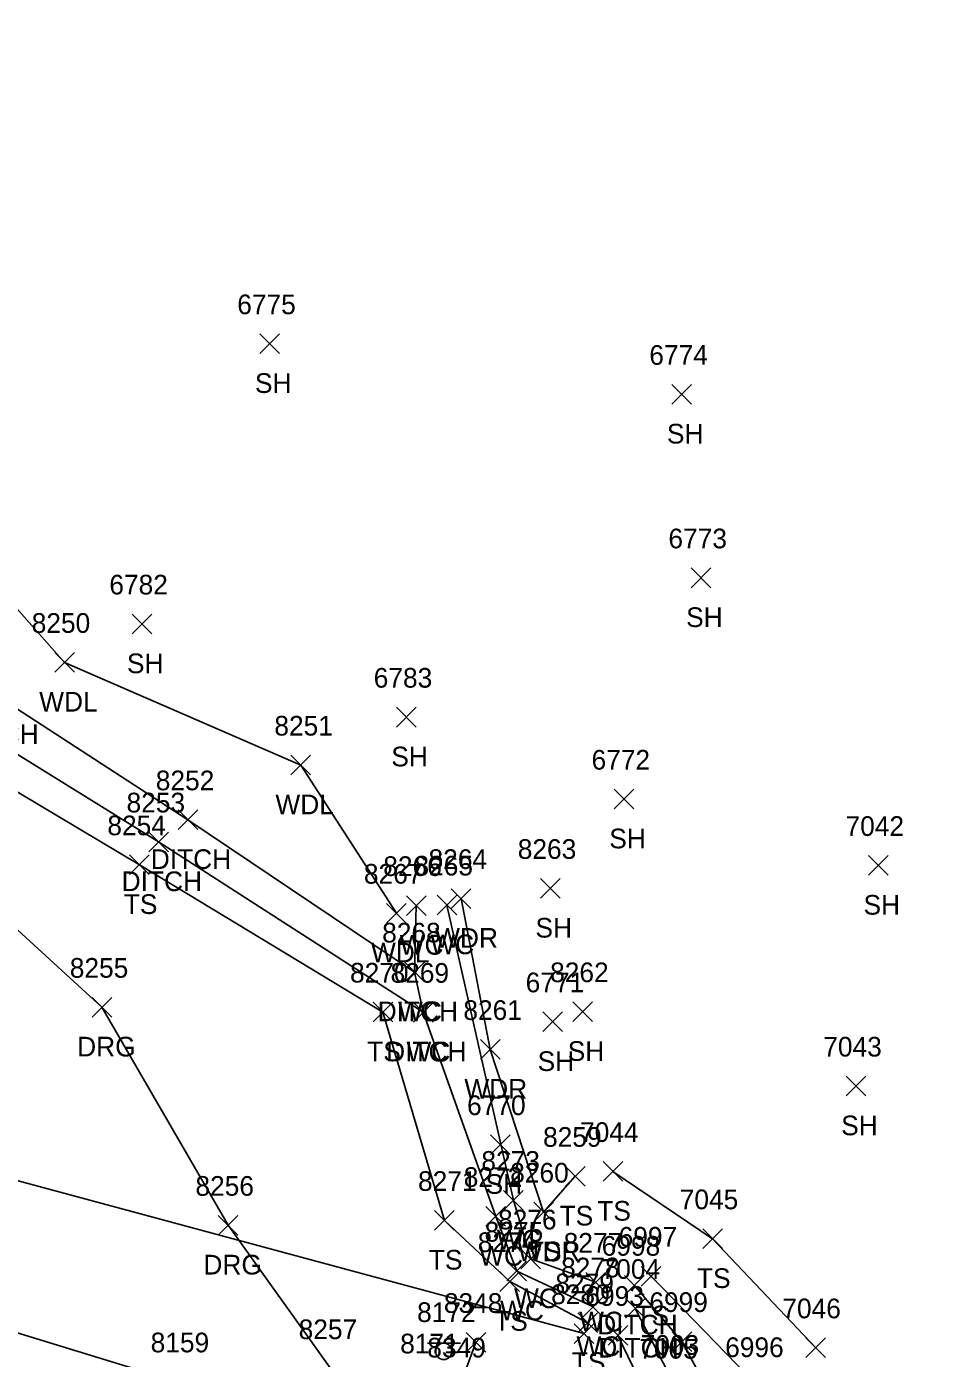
# Model space of a CAD drawing. Extents: x 1588028 to 1589597, y 137576 to 138176.
# Drawn here: x 1589112.3 to 1589205.2, y 137833.8 to 137969.2 of the extents above; entities that cross this region are included whole.
import ezdxf

# ---------------------------------------------------------------- set-up
doc = ezdxf.new("R2010")
doc.units = 0
for name, color, linetype in [('D_A', 7, 'Continuous'), ('D_I', 7, 'Continuous'), ('D_TIC', 7, 'Continuous'), ('DCP', 7, 'Continuous'), ('DD', 7, 'Continuous'), ('L_A', 7, 'Continuous'), ('L_I', 7, 'Continuous'), ('L_TIC', 7, 'Continuous'), ('LAWA', 7, 'Continuous'), ('LAWE', 7, 'Continuous'), ('LELB', 7, 'Continuous'), ('P_I', 7, 'Continuous'), ('PET', 7, 'Continuous'), ('R_A', 7, 'Continuous'), ('R_I', 7, 'Continuous'), ('R_TIC', 7, 'Continuous'), ('RDG', 7, 'Continuous'), ('S_I', 7, 'Continuous'), ('SSGN', 7, 'Continuous')]:
    doc.layers.add(name, color=color, linetype=linetype)

msp = doc.modelspace()

# ---------------------------------------------------------------- linework, layer by layer
at = {"layer": 'D_TIC'}
for points in [[(1589127.72, 137887.57), (1589129.72, 137889.57)], [(1589129.72, 137887.57), (1589127.72, 137889.57)], [(1589124.75, 137885.32), (1589126.75, 137887.32)], [(1589126.75, 137885.32), (1589124.75, 137887.32)], [(1589150.77, 137872.1), (1589152.77, 137874.1)], [(1589152.77, 137872.1), (1589150.77, 137874.1)], [(1589151.64, 137868.01), (1589153.64, 137870.01)], [(1589153.64, 137868.01), (1589151.64, 137870.01)], [(1589173.09, 137840.27), (1589175.09, 137842.27)], [(1589175.09, 137840.27), (1589173.09, 137842.27)], [(1589173.19, 137837.92), (1589175.19, 137839.92)], [(1589175.19, 137837.92), (1589173.19, 137839.92)], [(1589167.99, 137835.35), (1589169.99, 137837.35)], [(1589169.99, 137835.35), (1589167.99, 137837.35)], [(1589177.94, 137834.55), (1589179.94, 137836.55)], [(1589179.94, 137834.55), (1589177.94, 137836.55)]]:
    msp.add_lwpolyline(points, dxfattribs=at)
at = {"layer": 'DCP'}
msp.add_lwpolyline([(1589168.99, 137836.35), (1589071.86, 137862.56)], dxfattribs=at)
at = {"layer": 'DD'}
for points in [[(1589041.43, 137965.49), (1589078.53, 137926.76), (1589109.15, 137901.27), (1589128.72, 137888.57), (1589151.77, 137873.1)], [(1589038.34, 137962.57), (1589076.03, 137924.59), (1589104.4, 137899.54), (1589125.75, 137886.32), (1589152.64, 137869.01)], [(1589174.09, 137841.27), (1589178.94, 137835.55), (1589183.37, 137827.39), (1589182.25, 137825.97), (1589181.26, 137826.74), (1589178.15, 137831.2), (1589174.19, 137838.92)]]:
    msp.add_lwpolyline(points, dxfattribs=at)
at = {"layer": 'L_TIC'}
for points in [[(1589136.05, 137935.95), (1589138.05, 137937.95)], [(1589138.05, 137935.95), (1589136.05, 137937.95)], [(1589177.92, 137930.81), (1589179.92, 137932.81)], [(1589179.92, 137930.81), (1589177.92, 137932.81)], [(1589179.87, 137912.16), (1589181.87, 137914.16)], [(1589181.87, 137912.16), (1589179.87, 137914.16)], [(1589123.05, 137907.47), (1589125.05, 137909.47)], [(1589125.05, 137907.47), (1589123.05, 137909.47)], [(1589115.19, 137903.57), (1589117.19, 137905.57)], [(1589117.19, 137903.57), (1589115.19, 137905.57)], [(1589149.92, 137898), (1589151.92, 137900)], [(1589151.92, 137898), (1589149.92, 137900)], [(1589139.2, 137893.13), (1589141.2, 137895.13)], [(1589141.2, 137893.13), (1589139.2, 137895.13)], [(1589172.06, 137889.67), (1589174.06, 137891.67)], [(1589174.06, 137889.67), (1589172.06, 137891.67)], [(1589122.8, 137883), (1589124.8, 137885)], [(1589124.8, 137883), (1589122.8, 137885)], [(1589197.9, 137882.93), (1589199.9, 137884.93)], [(1589199.9, 137882.93), (1589197.9, 137884.93)], [(1589164.56, 137880.6), (1589166.56, 137882.6)], [(1589166.56, 137880.6), (1589164.56, 137882.6)], [(1589155.49, 137879.57), (1589157.49, 137881.57)], [(1589157.49, 137879.57), (1589155.49, 137881.57)], [(1589148.91, 137878.08), (1589150.91, 137880.08)], [(1589150.91, 137878.08), (1589148.91, 137880.08)], [(1589150.94, 137878.86), (1589152.94, 137880.86)], [(1589152.94, 137878.86), (1589150.94, 137880.86)], [(1589154.05, 137878.91), (1589156.05, 137880.91)], [(1589156.05, 137878.91), (1589154.05, 137880.91)], [(1589150.77, 137872.1), (1589152.77, 137874.1)], [(1589152.77, 137872.1), (1589150.77, 137874.1)], [(1589147.54, 137868.03), (1589149.54, 137870.03)], [(1589149.54, 137868.03), (1589147.54, 137870.03)], [(1589151.64, 137868.01), (1589153.64, 137870.01)], [(1589153.64, 137868.01), (1589151.64, 137870.01)], [(1589164.79, 137867.04), (1589166.79, 137869.04)], [(1589166.79, 137867.04), (1589164.79, 137869.04)], [(1589167.84, 137868.07), (1589169.84, 137870.07)], [(1589169.84, 137868.07), (1589167.84, 137870.07)], [(1589158.46, 137864.23), (1589160.46, 137866.23)], [(1589160.46, 137864.23), (1589158.46, 137866.23)], [(1589195.64, 137860.51), (1589197.64, 137862.51)], [(1589197.64, 137860.51), (1589195.64, 137862.51)], [(1589159.49, 137854.56), (1589161.49, 137856.56)], [(1589161.49, 137854.56), (1589159.49, 137856.56)], [(1589167.09, 137851.34), (1589169.09, 137853.34)], [(1589169.09, 137851.34), (1589167.09, 137853.34)], [(1589170.92, 137851.83), (1589172.92, 137853.83)], [(1589172.92, 137851.83), (1589170.92, 137853.83)], [(1589160.81, 137848.9), (1589162.81, 137850.9)], [(1589162.81, 137848.9), (1589160.81, 137850.9)], [(1589153.8, 137846.86), (1589155.8, 137848.86)], [(1589155.8, 137846.86), (1589153.8, 137848.86)], [(1589159.02, 137847.26), (1589161.02, 137849.26)], [(1589161.02, 137847.26), (1589159.02, 137849.26)], [(1589163.87, 137847.7), (1589165.87, 137849.7)], [(1589165.87, 137847.7), (1589163.87, 137849.7)], [(1589163.87, 137847.7), (1589165.87, 137849.7)], [(1589165.87, 137847.7), (1589163.87, 137849.7)], [(1589181.05, 137844.99), (1589183.05, 137846.99)], [(1589183.05, 137844.99), (1589181.05, 137846.99)], [(1589162.57, 137842.94), (1589164.57, 137844.94)], [(1589164.57, 137842.94), (1589162.57, 137844.94)], [(1589161.14, 137841.7), (1589163.14, 137843.7)], [(1589163.14, 137841.7), (1589161.14, 137843.7)], [(1589174.8, 137841.19), (1589176.8, 137843.19)], [(1589176.8, 137841.19), (1589174.8, 137843.19)], [(1589160.44, 137840.64), (1589162.44, 137842.64)], [(1589162.44, 137840.64), (1589160.44, 137842.64)], [(1589169.17, 137840.58), (1589171.17, 137842.58)], [(1589171.17, 137840.58), (1589169.17, 137842.58)], [(1589168.91, 137838.07), (1589170.91, 137840.07)], [(1589170.91, 137838.07), (1589168.91, 137840.07)], [(1589168.34, 137836.46), (1589170.34, 137838.46)], [(1589170.34, 137836.46), (1589168.34, 137838.46)], [(1589157, 137834.46), (1589159, 137836.46)], [(1589159, 137834.46), (1589157, 137836.46)], [(1589171.43, 137835.17), (1589173.43, 137837.17)], [(1589173.43, 137835.17), (1589171.43, 137837.17)], [(1589191.53, 137833.91), (1589193.53, 137835.91)], [(1589193.53, 137833.91), (1589191.53, 137835.91)]]:
    msp.add_lwpolyline(points, dxfattribs=at)
at = {"layer": 'LAWA'}
for points in [[(1589050.56, 137971.24), (1589083.91, 137941.07), (1589116.19, 137904.57), (1589140.2, 137894.13), (1589149.91, 137879.08)], [(1589164.87, 137848.7), (1589159.46, 137865.23), (1589156.49, 137880.57)]]:
    msp.add_lwpolyline(points, dxfattribs=at)
at = {"layer": 'LAWE'}
for points in [[(1589151.94, 137879.86), (1589151.77, 137873.1), (1589152.64, 137869.01), (1589160.02, 137848.26), (1589162.14, 137842.7), (1589169.91, 137839.07)], [(1589155.05, 137879.91), (1589161.81, 137849.9), (1589163.57, 137843.94), (1589170.17, 137841.58)]]:
    msp.add_lwpolyline(points, dxfattribs=at)
at = {"layer": 'LELB'}
for points in [[(1589034.42, 137961.01), (1589073.51, 137921.6), (1589099.4, 137898.53), (1589123.8, 137884), (1589148.54, 137869.03), (1589154.8, 137847.86), (1589161.44, 137841.64), (1589169.34, 137837.46)], [(1589171.92, 137852.83), (1589182.05, 137845.99), (1589192.53, 137834.91)], [(1589168.09, 137852.34), (1589164.87, 137848.7)], [(1589172.43, 137836.17), (1589176.44, 137827.84), (1589184.21, 137823.17), (1589186.69, 137830.97), (1589175.8, 137842.19)], [(1589158, 137835.46), (1589156.32, 137830.93), (1589175.62, 137825.43), (1589182.94, 137822.51), (1589209.46, 137809.41), (1589234.23, 137800.33), (1589267.46, 137786.74), (1589294.29, 137776.74), (1589322.35, 137767.05), (1589346.37, 137758.08), (1589352.86, 137754.06), (1589353.51, 137751.68), (1589354.61, 137751.57), (1589355.75, 137752.57)]]:
    msp.add_lwpolyline(points, dxfattribs=at)
at = {"layer": 'PET'}
msp.add_lwpolyline([(1588976.42, 137837.98), (1588964.71, 137855.4), (1588953.74, 137871.46), (1588980.82, 137866.91), (1589021.21, 137859.55), (1589054.58, 137852.92), (1589087.36, 137843.77), (1589127.64, 137831.45), (1589150.05, 137824.37), (1589196.14, 137808.72), (1589243.87, 137790.96), (1589276.87, 137778.08), (1589322.25, 137759.62), (1589367.82, 137740.82), (1589401.87, 137726.11), (1589432.81, 137712.85), (1589459.76, 137701.46)], dxfattribs=at)
at = {"layer": 'R_TIC'}
for points in [[(1589118.98, 137868.52), (1589120.98, 137870.52)], [(1589120.98, 137868.52), (1589118.98, 137870.52)], [(1589131.81, 137846.36), (1589133.81, 137848.36)], [(1589133.81, 137846.36), (1589131.81, 137848.36)]]:
    msp.add_lwpolyline(points, dxfattribs=at)
at = {"layer": 'RDG'}
msp.add_lwpolyline([(1589030.3, 137954.92), (1589069.21, 137915.71), (1589093.48, 137893.77), (1589119.98, 137869.52), (1589132.81, 137847.36), (1589143.24, 137832.79), (1589147.71, 137827.91)], dxfattribs=at)
at = {"layer": 'SSGN'}
for p, q in [((1589153.08, 137835.38), (1589156.42, 137835.38)), ((1589154.73, 137834.55), (1589154.73, 137834.55))]:
    msp.add_line(p, q, dxfattribs=at)
msp.add_circle((1589154.73, 137834.55), 0.833, dxfattribs=at)

# ---------------------------------------------------------------- texts
at = {"layer": 'D_A'}
for p in [(1589105.39, 137896.27), (1589124.95, 137883.57), (1589121.99, 137881.32), (1589148.01, 137868.1), (1589148.87, 137864.01), (1589170.33, 137836.27), (1589170.43, 137833.92)]:
    msp.add_text('DITCH', height=2, dxfattribs=at).set_placement(p)
at = {"layer": 'D_I'}
for s, p in [('8252', (1589125.46, 137891.57)), ('8253', (1589122.49, 137889.32)), ('8268', (1589148.47, 137876.1)), ('8269', (1589149.32, 137872.01)), ('6998', (1589170.78, 137844.27)), ('7004', (1589170.77, 137841.92)), ('8280', (1589165.64, 137839.35)), ('6999', (1589175.62, 137838.55)), ('7005', (1589174.6, 137833.81)), ('7003', (1589174.74, 137834.2))]:
    msp.add_text(s, height=2, dxfattribs=at).set_placement(p)
at = {"layer": 'L_A'}
for s, p in [('SH', (1589135.54, 137931.95)), ('SH', (1589177.41, 137926.81)), ('SH', (1589179.36, 137908.16)), ('SH', (1589122.53, 137903.47)), ('WDL', (1589113.61, 137899.57)), ('SH', (1589149.4, 137894)), ('WDL', (1589137.62, 137889.13)), ('SH', (1589171.55, 137885.67)), ('TS', (1589122.21, 137879)), ('SH', (1589197.39, 137878.93)), ('SH', (1589164.05, 137876.6)), ('WDR', (1589153.85, 137875.57)), ('WDL', (1589147.33, 137874.08)), ('WC', (1589150.25, 137874.86)), ('WC', (1589153.36, 137874.91)), ('WC', (1589150.08, 137868.1)), ('TS', (1589146.95, 137864.03)), ('WC', (1589150.94, 137864.01)), ('SH', (1589164.27, 137863.04)), ('SH', (1589167.33, 137864.07)), ('WDR', (1589156.82, 137860.23)), ('SH', (1589195.12, 137856.51)), ('SH', (1589158.98, 137850.56)), ('TS', (1589166.5, 137847.34)), ('TS', (1589170.33, 137847.83)), ('WC', (1589160.12, 137844.9)), ('TS', (1589153.21, 137842.86)), ('WC', (1589158.32, 137843.26)), ('WDR', (1589162.23, 137843.7)), ('TS', (1589163.28, 137843.7)), ('TS', (1589180.46, 137840.99)), ('WC', (1589161.87, 137838.94)), ('WC', (1589160.45, 137837.7)), ('TS', (1589174.21, 137837.19)), ('TS', (1589159.85, 137836.64)), ('WC', (1589168.48, 137836.58)), ('WC', (1589168.21, 137834.07)), ('TS', (1589167.75, 137832.46))]:
    msp.add_text(s, height=2, dxfattribs=at).set_placement(p)
at = {"layer": 'L_I'}
for s, p in [('6775', (1589133.74, 137939.95)), ('6774', (1589175.62, 137934.81)), ('6773', (1589177.56, 137916.16)), ('6782', (1589120.74, 137911.47)), ('8250', (1589112.85, 137907.57)), ('6783', (1589147.61, 137902)), ('8251', (1589137.51, 137897.13)), ('6772', (1589169.75, 137893.67)), ('8254', (1589120.54, 137887)), ('7042', (1589195.56, 137886.93)), ('8263', (1589162.25, 137884.6)), ('8264', (1589153.18, 137883.57)), ('8267', (1589146.61, 137882.08)), ('8266', (1589148.58, 137882.86)), ('8265', (1589151.75, 137882.91)), ('8268', (1589148.47, 137876.1)), ('8270', (1589145.2, 137872.03)), ('8269', (1589149.32, 137872.01)), ('6771', (1589163.05, 137871.04)), ('8262', (1589165.54, 137872.07)), ('8261', (1589156.72, 137868.23)), ('7043', (1589193.3, 137864.51)), ('6770', (1589157.1, 137858.56)), ('8259', (1589164.82, 137855.34)), ('7044', (1589168.58, 137855.83)), ('8273', (1589158.55, 137852.9)), ('8271', (1589152.11, 137850.86)), ('8272', (1589156.76, 137851.26)), ('8260', (1589161.48, 137851.7)), ('8260', (1589161.48, 137851.7)), ('7045', (1589178.71, 137848.99)), ('8276', (1589160.25, 137846.94)), ('8275', (1589158.88, 137845.7)), ('6997', (1589172.5, 137845.19)), ('8274', (1589158.18, 137844.64)), ('8277', (1589166.91, 137844.58)), ('8278', (1589166.65, 137842.07)), ('8279', (1589166.07, 137840.46)), ('8348', (1589154.74, 137838.46)), ('6993', (1589169.12, 137839.17)), ('7046', (1589189.14, 137837.91)), ('8349', (1589153.06, 137833.93)), ('6996', (1589183.33, 137833.97))]:
    msp.add_text(s, height=2, dxfattribs=at).set_placement(p)
at = {"layer": 'P_I'}
msp.add_text('8159', height=2, dxfattribs=at).set_placement((1589124.94, 137834.45))
at = {"layer": 'R_A'}
for p in [(1589117.47, 137864.52), (1589130.3, 137842.36)]:
    msp.add_text('DRG', height=2, dxfattribs=at).set_placement(p)
at = {"layer": 'R_I'}
for s, p in [('8255', (1589116.72, 137872.52)), ('8256', (1589129.49, 137850.36)), ('8257', (1589139.98, 137835.79))]:
    msp.add_text(s, height=2, dxfattribs=at).set_placement(p)
at = {"layer": 'S_I'}
for s, p in [('8172', (1589152.02, 137837.53)), ('8171', (1589150.3, 137834.34))]:
    msp.add_text(s, height=2, dxfattribs=at).set_placement(p)

doc.saveas('drawing.dxf')
